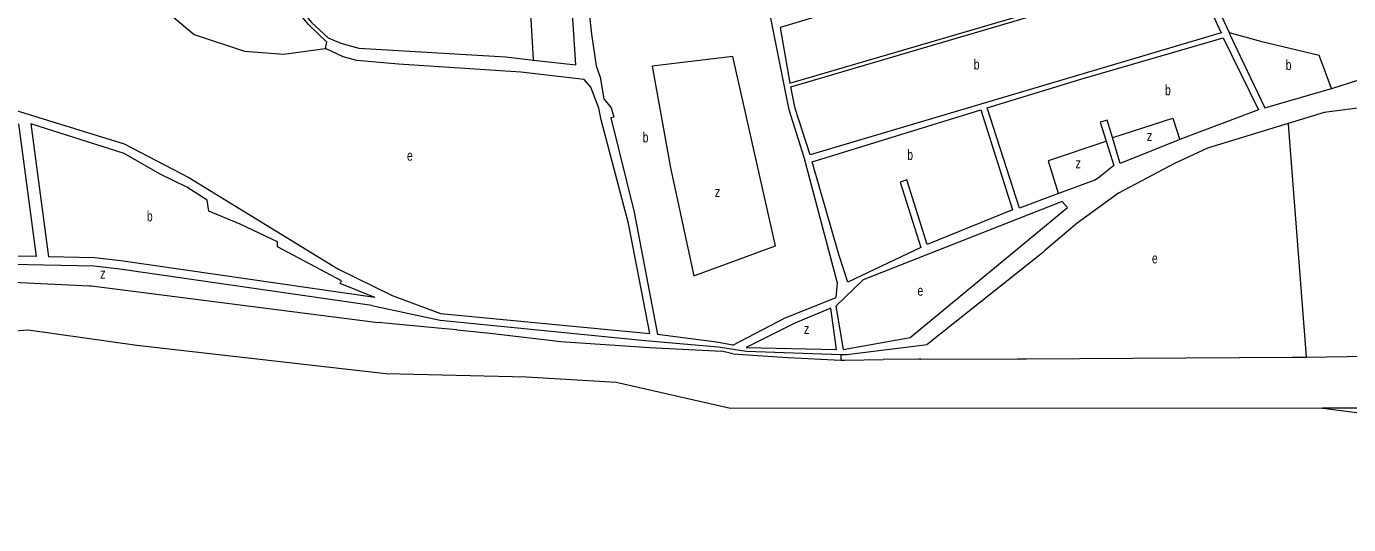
# Model space of a CAD drawing. Extents: x 639657 to 671642, y 222838 to 252123.
# Drawn here: x 640346 to 641627, y 234105 to 234587 of the extents above; entities that cross this region are included whole.
import ezdxf

# ---------------------------------------------------------------- set-up
doc = ezdxf.new("R2010")
doc.units = 0
doc.header["$LTSCALE"] = 4
doc.layers.add('1', color=7, linetype='Continuous', lineweight=13)
doc.layers.add('21', color=7, linetype='Continuous', lineweight=13)
doc.layers.add('7', color=7, linetype='Continuous')

msp = doc.modelspace()

# ---------------------------------------------------------------- linework, layer by layer
at = {"layer": '1'}
for p, q in [((640338.447, 234492.773), (640355.561, 234364.356)), ((640350.308, 234492.881), (640367.465, 234364.139)), ((640409.34, 234336.135), (640686.859, 234300.585)), ((640680.963, 234316.919), (640746.91, 234302.944)), ((640747.477, 234309.2), (640950.264, 234290.059)), ((641137.532, 234274.55), (641202.326, 234286.24)), ((640950.032, 234276.496), (641020.122, 234273.01)), ((641030.605, 234270.134), (641020.122, 234273.01)), ((641043.479, 234276.524), (641131.197, 234274.616)), ((641141.22, 234269.477), (641219.072, 234279.351)), ((641139.292, 234264.021), (641176.154, 234264.685))]:
    msp.add_line(p, q, dxfattribs=at)
for points in [[(641673.708, 235149.068), (641656.841, 235142.655), (641566.79, 235091.522), (641472.306, 235069.593), (641340.04, 235044.068), (641302.577, 235038.039), (641308.302, 235013.818), (641511.439, 234581.317)], [(640636.078, 234565.886), (640637.262, 234572.086), (640619.587, 234588.922), (640575.078, 234642.936), (640558.402, 234683.038), (640560.906, 234691.701)], [(640830.872, 234661.368), (640817.442, 234660.548), (640772.51, 234645.437), (640766.314, 234644.889), (640751.996, 234679.205), (640706.508, 234654.549), (640669.228, 234651.972), (640634.471, 234652.457), (640597.959, 234658.006), (640582.287, 234662.065), (640567.792, 234673.542), (640578.63, 234643.771), (640622.522, 234590.971), (640638.561, 234576.053), (640650.784, 234570.854), (640668.086, 234566.196), (640810.807, 234557.683), (640837.335, 234554.679)], [(640837.335, 234554.679), (640878.63, 234550.003), (640870.997, 234663.818)], [(641030.64, 234278.547), (641081.42, 234305.28), (641130.799, 234324.683), (641131.939, 234338.799), (641099.853, 234460.292), (641085.163, 234506.38), (641061.005, 234627.721), (640893.819, 234613.643), (640890.275, 234611.488), (640893.807, 234579.842), (640898.248, 234549.116), (640902.171, 234538.179), (640905.644, 234516.988), (640912.806, 234508.407), (640915.193, 234499.49), (640912.556, 234498.661), (640934.92, 234407.251), (640957.587, 234288.952)], [(641511.439, 234581.317), (641512.389, 234579.317), (641545.994, 234508.561), (641610.722, 234527.049)], [(640950.264, 234290.059), (640929.696, 234396.559), (640902.913, 234496.67), (640900.919, 234507.923), (640892.978, 234528.477), (640886.534, 234535.946), (640825.219, 234542.856), (640706.585, 234550.814), (640666.223, 234554.206), (640653.094, 234557.775), (640636.078, 234565.886)], [(641277.236, 234508.364), (641368.004, 234536.232), (641505.777, 234576.205), (641540.111, 234506.595), (641477.342, 234482.943), (641463.803, 234477.588)], [(640278.553, 234539.795), (640283.846, 234533.249), (640318.012, 234511.343), (640440.879, 234473.672), (640503.357, 234440.887), (640647.952, 234352.403), (640700.531, 234326.861), (640747.477, 234309.2)], [(641610.722, 234527.049), (641611.222, 234527.208), (641684.751, 234550.538)], [(641737.945, 234534.04), (641724.721, 234530.226), (641648.521, 234509.633), (641603.537, 234503.758), (641568.8, 234493.143)], [(641141.995, 234339.575), (641133.409, 234366.316), (641107.599, 234456.282), (641271.102, 234506.481)], [(641271.102, 234506.481), (641301.751, 234409.634), (641219.02, 234376.007), (641199.359, 234438.608), (641192.766, 234436.332), (641212.837, 234373.226), (641141.995, 234339.575)], [(641346.184, 234425.383), (641308.449, 234411.302), (641277.236, 234508.364)], [(640683.716, 234324.808), (640650.266, 234338.41), (640651.572, 234341.058), (640589.299, 234373.743), (640589.27, 234378.818), (640553.099, 234395.839), (640522.848, 234408.228), (640521.262, 234419.18), (640501.579, 234431.74), (640475.698, 234444.057), (640440.831, 234464.232), (640350.308, 234492.881)], [(641568.8, 234493.143), (641490.528, 234469.224), (641458.703, 234454.401), (641404.498, 234425.831), (641364.219, 234396.642), (641336.86, 234373.671)], [(641398.407, 234479.548), (641393.328, 234496.506), (641386.429, 234494.634), (641392.448, 234476.005)], [(641392.448, 234476.005), (641399.977, 234452.7), (641384.601, 234440.318), (641381.258, 234438.47), (641346.184, 234425.383)], [(641463.803, 234477.588), (641405.86, 234454.667), (641398.407, 234479.548)], [(641202.326, 234286.24), (641354.784, 234411.806), (641349.772, 234417.66), (641156.92, 234341.803), (641130.541, 234316.358), (641137.532, 234274.55)], [(641336.86, 234373.671), (641334.86, 234371.801), (641332.766, 234369.844)], [(640355.561, 234364.356), (640331.035, 234364.802), (640248.367, 234357.997)], [(640683.716, 234324.808), (640437.764, 234360.384), (640412.002, 234363.329), (640367.465, 234364.139)], [(641332.766, 234369.844), (641330.766, 234368.096), (641219.072, 234279.351)], [(640680.963, 234316.919), (640436.711, 234352.249), (640411.46, 234355.136), (640331.297, 234356.594), (640215.592, 234347.07), (640175.29, 234341.938)], [(640247.679, 234333.461), (640249.679, 234333.602), (640333.412, 234339.499), (640407.34, 234336.224), (640409.34, 234336.135)], [(641601.897, 234217.647), (641028.463, 234217.456), (640917.676, 234242.559), (640830.821, 234247.714), (640694.503, 234251.077), (640452.959, 234278.395), (640347.94, 234293.104), (640259.724, 234286.8), (640041.284, 234261.584), (639961.469, 234257.381), (639938.365, 234259.483), (639896.358, 234295.206), (639906.178, 234326.394), (639906.808, 234328.394)], [(641131.197, 234274.616), (641125.674, 234314.398), (641090.697, 234299.96), (641043.479, 234276.524)], [(640763.103, 234293.371), (640748.382, 234294.844), (640686.859, 234300.585)], [(640746.91, 234302.944), (640945.647, 234283.061), (641016.309, 234277.17), (641043.872, 234272.986)], [(640763.103, 234293.371), (640795.49, 234290.425), (640863.944, 234282.325), (640950.032, 234276.496)], [(641030.64, 234278.547), (641014.837, 234281.588), (640957.587, 234288.952)], [(641030.605, 234270.134), (641083.771, 234266.724), (641135.187, 234264.221), (641139.292, 234264.021)], [(641043.872, 234272.986), (641135.187, 234269.694), (641141.22, 234269.477)], [(641586.245, 234267.169), (641962.436, 234273.142), (642028.877, 234276.275)], [(641212.837, 234265.025), (641210.837, 234265.006), (641176.154, 234264.685)], [(641212.837, 234265.025), (641306.052, 234265.431), (641308.052, 234265.44)], [(641308.052, 234265.44), (641312.758, 234265.542), (641314.758, 234265.585)], [(641314.758, 234265.585), (641572.964, 234266.958), (641586.245, 234267.169)], [(643119.12, 234224.471), (642972.745, 234230.146), (642938.301, 234237.503), (642932.19, 234218.865), (642859.711, 234229.772), (642653.107, 234227.915), (642617.407, 234224.107), (642056.301, 234221.39), (642032.886, 234208.556), (642007.734, 234217.783), (641601.897, 234217.647)]]:
    msp.add_lwpolyline(points, dxfattribs=at)
for points in [[(641076.494, 234586.225), (641085.728, 234532.368), (641421.532, 234630.773), (641370.887, 234673.786)], [(641105.529, 234462.866), (641090.947, 234507.838), (641086.765, 234528.619), (641424.19, 234628.05), (641438.968, 234620.33), (641472.662, 234610.095), (641495.178, 234599.685), (641503.719, 234580.861)]]:
    msp.add_lwpolyline(points, close=True, dxfattribs=at)
at = {"layer": '21'}
for p, q in [((641511.439, 234581.317), (641541.87, 234572.988)), ((641541.87, 234572.988), (641598.752, 234559.452))]:
    msp.add_line(p, q, dxfattribs=at)
for points in [[(640407.221, 234657.528), (640407.721, 234657.228), (640421.943, 234648.691), (640427.831, 234629.544), (640436.664, 234623.653), (640455.801, 234638.381), (640466.106, 234650.164), (640469.051, 234648.691), (640469.051, 234626.599), (640474.939, 234607.452), (640508.798, 234579.469), (640557.378, 234563.268), (640595.653, 234560.322), (640635.578, 234565.817), (640636.078, 234565.886)], [(640830.872, 234661.368), (640830.902, 234660.868), (640837.305, 234555.179), (640837.335, 234554.679)], [(641610.722, 234527.049), (641599.491, 234557.452), (641598.752, 234559.452)], [(641398.407, 234479.548), (641398.907, 234479.71), (641456.847, 234498.464), (641463.561, 234478.313), (641463.803, 234477.588)], [(641568.8, 234493.143), (641568.839, 234492.643), (641586.217, 234267.529), (641586.245, 234267.169)], [(641392.448, 234476.005), (641391.948, 234475.838), (641336.133, 234457.225), (641346.026, 234425.883), (641346.184, 234425.383)], [(641135.187, 234269.694), (641135.187, 234269.194), (641135.187, 234264.721), (641135.187, 234264.221)], [(641601.897, 234217.647), (641602.401, 234217.583), (642053.12, 234160.315), (642243.981, 234129.401), (642403.622, 234090.154), (642510.512, 234068.829), (642485.176, 233865.921), (642484.552, 233860.921)]]:
    msp.add_lwpolyline(points, dxfattribs=at)
msp.add_lwpolyline([(640952.391, 234548.707), (640970.203, 234450.225), (640993.005, 234345.812), (641071.936, 234374.767), (641030.717, 234558.148)], close=True, dxfattribs=at)

# ---------------------------------------------------------------- texts
at = {"layer": '7'}
for s, width, p in [('b', 0.75, (641264.078, 234545.458)), ('b', 0.75, (641566.415, 234544.939)), ('b', 0.75, (641449.487, 234520.556)), ('b', 0.75, (640943.262, 234474.933)), ('z', 0.8, (641431.821, 234476.372)), ('e', 0.75, (640714.896, 234457.225)), ('b', 0.75, (641199.658, 234457.89)), ('z', 0.8, (641362.631, 234449.861)), ('z', 0.8, (641013.177, 234422.148)), ('b', 0.75, (640462.853, 234398.493)), ('e', 0.75, (641436.746, 234357.795)), ('z', 0.8, (640417.526, 234343.083)), ('e', 0.75, (641209.627, 234326.509)), ('z', 0.8, (641099.473, 234289.603))]:
    msp.add_text(s, height=10, dxfattribs=dict(at, width=width)).set_placement(p)

doc.saveas('drawing.dxf')
